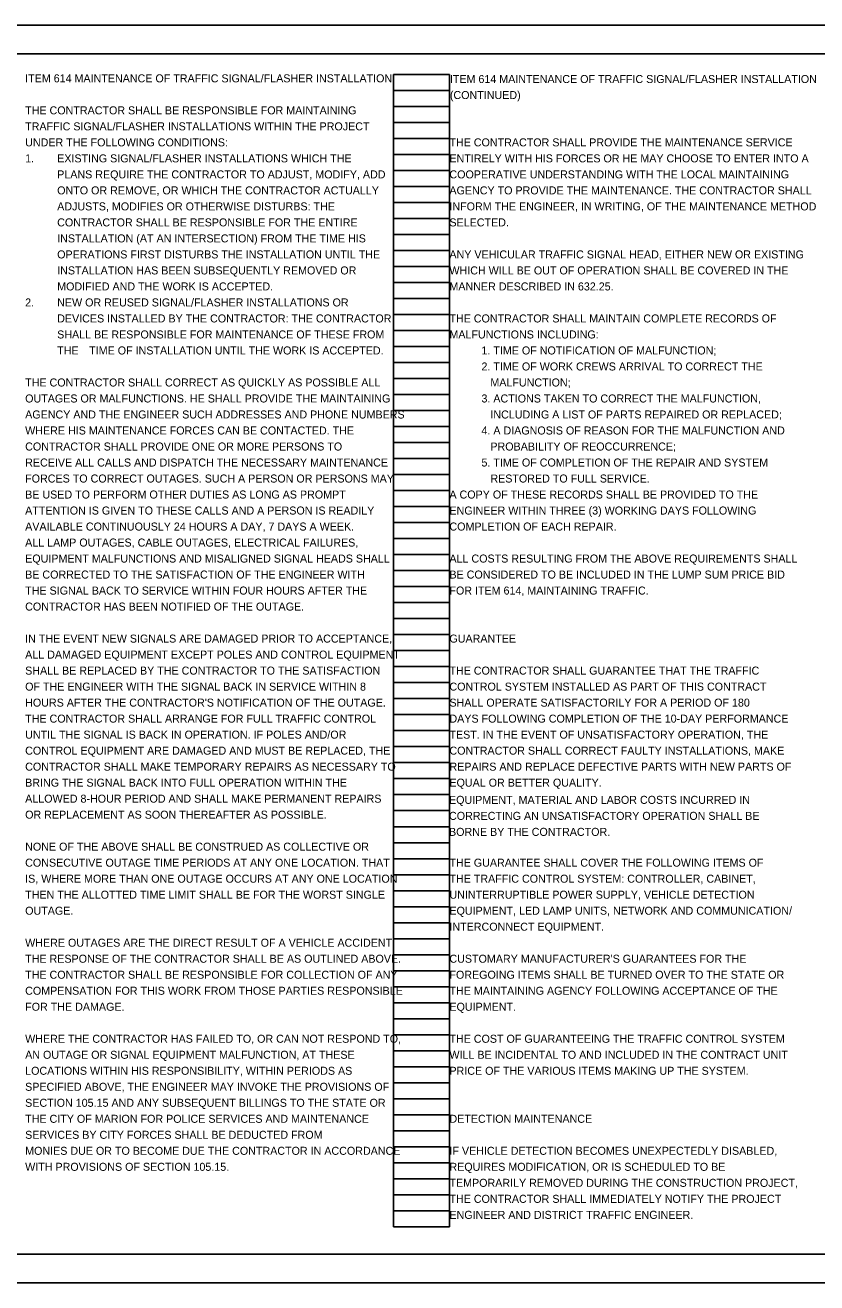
# Model space of a CAD drawing. Extents: x -11.8 to 65.2, y -26.4 to 34.6.
# Drawn here: x 10.32 to 24.17, y 0 to 22 of the extents above; entities that cross this region are included whole.
import ezdxf

# ---------------------------------------------------------------- set-up
doc = ezdxf.new("R2010")
doc.units = 0
for name, color, linetype in [('SH_Border', 7, 'Continuous'), ('SH_Cut_Line', 7, 'Continuous'), ('SH_Data', 7, 'Continuous'), ('SH_Text', 7, 'Continuous')]:
    doc.layers.add(name, color=color, linetype=linetype)

msp = doc.modelspace()

# ---------------------------------------------------------------- linework, layer by layer
at = {"layer": 'SH_Border'}
msp.add_lwpolyline([(2.001, 21.5), (33.501, 21.5), (33.501, 0.5), (2.001, 0.5)], close=True, dxfattribs=at)
at = {"layer": 'SH_Cut_Line'}
msp.add_lwpolyline([(0.001, 0), (34.001, 0), (34.001, 22), (0.001, 22)], close=True, dxfattribs=at)
at = {"layer": 'SH_Data'}
for p, q in [((16.761, 0.98), (16.761, 21.14)), ((16.761, 21.14), (17.741, 21.14)), ((17.741, 0.98), (17.741, 21.14)), ((16.761, 20.86), (17.741, 20.86)), ((16.761, 20.58), (17.741, 20.58)), ((16.761, 20.3), (17.741, 20.3)), ((16.761, 20.02), (17.741, 20.02)), ((16.761, 19.74), (17.741, 19.74)), ((16.761, 19.46), (17.741, 19.46)), ((16.761, 19.18), (17.741, 19.18)), ((16.761, 18.9), (17.741, 18.9)), ((16.761, 18.62), (17.741, 18.62)), ((16.761, 18.34), (17.741, 18.34)), ((16.761, 18.06), (17.741, 18.06)), ((16.761, 17.78), (17.741, 17.78)), ((16.761, 17.5), (17.741, 17.5)), ((16.761, 17.22), (17.741, 17.22)), ((16.761, 16.94), (17.741, 16.94)), ((16.761, 16.66), (17.741, 16.66)), ((16.761, 16.38), (17.741, 16.38)), ((16.761, 16.1), (17.741, 16.1)), ((16.761, 15.82), (17.741, 15.82)), ((16.761, 15.54), (17.741, 15.54)), ((16.761, 15.26), (17.741, 15.26)), ((16.761, 14.98), (17.741, 14.98)), ((16.761, 14.7), (17.741, 14.7)), ((16.761, 14.42), (17.741, 14.42)), ((16.761, 14.14), (17.741, 14.14)), ((16.761, 13.86), (17.741, 13.86)), ((16.761, 13.58), (17.741, 13.58)), ((16.761, 13.3), (17.741, 13.3)), ((16.761, 13.02), (17.741, 13.02)), ((16.761, 12.74), (17.741, 12.74)), ((16.761, 12.46), (17.741, 12.46)), ((16.761, 12.18), (17.741, 12.18)), ((16.761, 11.9), (17.741, 11.9)), ((16.761, 11.62), (17.741, 11.62)), ((16.761, 11.34), (17.741, 11.34)), ((16.761, 11.06), (17.741, 11.06)), ((16.761, 10.78), (17.741, 10.78)), ((16.761, 10.5), (17.741, 10.5)), ((16.761, 10.22), (17.741, 10.22)), ((16.761, 9.94), (17.741, 9.94)), ((16.761, 9.66), (17.741, 9.66)), ((16.761, 9.38), (17.741, 9.38)), ((16.761, 9.1), (17.741, 9.1)), ((16.761, 8.82), (17.741, 8.82)), ((16.761, 8.54), (17.741, 8.54)), ((16.761, 8.26), (17.741, 8.26)), ((16.761, 7.98), (17.741, 7.98)), ((16.761, 7.7), (17.741, 7.7)), ((16.761, 7.42), (17.741, 7.42)), ((16.761, 7.14), (17.741, 7.14)), ((16.761, 6.86), (17.741, 6.86)), ((16.761, 6.58), (17.741, 6.58)), ((16.761, 6.3), (17.741, 6.3)), ((16.761, 6.02), (17.741, 6.02)), ((16.761, 5.74), (17.741, 5.74)), ((16.761, 5.46), (17.741, 5.46)), ((16.761, 5.18), (17.741, 5.18)), ((16.761, 4.9), (17.741, 4.9)), ((16.761, 4.62), (17.741, 4.62)), ((16.761, 4.34), (17.741, 4.34)), ((16.761, 4.06), (17.741, 4.06)), ((16.761, 3.78), (17.741, 3.78)), ((16.761, 3.5), (17.741, 3.5)), ((16.761, 3.22), (17.741, 3.22)), ((16.761, 2.94), (17.741, 2.94)), ((16.761, 2.66), (17.741, 2.66)), ((16.761, 2.38), (17.741, 2.38)), ((16.761, 2.1), (17.741, 2.1)), ((16.761, 1.82), (17.741, 1.82)), ((16.761, 1.54), (17.741, 1.54)), ((16.761, 1.26), (17.741, 1.26)), ((16.761, 0.98), (17.741, 0.98))]:
    msp.add_line(p, q, dxfattribs=at)

# ---------------------------------------------------------------- texts
at = {"layer": 'SH_Text'}
for s, p in [('ITEM 614 MAINTENANCE OF TRAFFIC SIGNAL/FLASHER INSTALLATION', (10.321, 21)), ('ITEM 614 MAINTENANCE OF TRAFFIC SIGNAL/FLASHER INSTALLATION', (17.749, 20.988)), ('(CONTINUED)', (17.749, 20.708)), ('THE CONTRACTOR SHALL BE RESPONSIBLE FOR MAINTAINING ', (10.321, 20.44)), ('TRAFFIC SIGNAL/FLASHER INSTALLATIONS WITHIN THE PROJECT ', (10.321, 20.16)), ('UNDER THE FOLLOWING CONDITIONS:', (10.321, 19.88)), ('THE CONTRACTOR SHALL PROVIDE THE MAINTENANCE SERVICE ', (17.741, 19.88)), ('1.', (10.321, 19.6)), ('EXISTING SIGNAL/FLASHER INSTALLATIONS WHICH THE ', (10.881, 19.6)), ('ENTIRELY WITH HIS FORCES OR HE MAY CHOOSE TO ENTER INTO A ', (17.741, 19.6)), ('PLANS REQUIRE THE CONTRACTOR TO ADJUST, MODIFY, ADD ', (10.881, 19.32)), ('COOPERATIVE UNDERSTANDING WITH THE LOCAL MAINTAINING ', (17.741, 19.32)), ('ONTO OR REMOVE, OR WHICH THE CONTRACTOR ACTUALLY ', (10.881, 19.04)), ('AGENCY TO PROVIDE THE MAINTENANCE. THE CONTRACTOR SHALL ', (17.741, 19.04)), ('ADJUSTS, MODIFIES OR OTHERWISE DISTURBS: THE ', (10.881, 18.76)), ('INFORM THE ENGINEER, IN WRITING, OF THE MAINTENANCE METHOD ', (17.741, 18.76)), ('CONTRACTOR SHALL BE RESPONSIBLE FOR THE ENTIRE ', (10.881, 18.48)), ('SELECTED. ', (17.741, 18.48)), ('INSTALLATION (AT AN INTERSECTION) FROM THE TIME HIS ', (10.881, 18.2)), ('OPERATIONS FIRST DISTURBS THE INSTALLATION UNTIL THE ', (10.881, 17.92)), ('ANY VEHICULAR TRAFFIC SIGNAL HEAD, EITHER NEW OR EXISTING ', (17.741, 17.92)), ('INSTALLATION HAS BEEN SUBSEQUENTLY REMOVED OR ', (10.881, 17.64)), ('WHICH WILL BE OUT OF OPERATION SHALL BE COVERED IN THE ', (17.741, 17.64)), ('MODIFIED AND THE WORK IS ACCEPTED.', (10.881, 17.36)), ('MANNER DESCRIBED IN 632.25.', (17.741, 17.36)), ('2.', (10.321, 17.08)), ('NEW OR REUSED SIGNAL/FLASHER INSTALLATIONS OR ', (10.881, 17.08)), ('DEVICES INSTALLED BY THE CONTRACTOR: THE CONTRACTOR ', (10.881, 16.8)), ('THE CONTRACTOR SHALL MAINTAIN COMPLETE RECORDS OF ', (17.741, 16.8)), ('SHALL BE RESPONSIBLE FOR MAINTENANCE OF THESE FROM ', (10.881, 16.52)), ('MALFUNCTIONS INCLUDING:', (17.741, 16.52)), ('THE ', (10.881, 16.24)), ('TIME OF INSTALLATION UNTIL THE WORK IS ACCEPTED. ', (11.441, 16.24)), ('1. TIME OF NOTIFICATION OF MALFUNCTION;', (18.301, 16.24)), ('2. TIME OF WORK CREWS ARRIVAL TO CORRECT THE ', (18.301, 15.96)), ('THE CONTRACTOR SHALL CORRECT AS QUICKLY AS POSSIBLE ALL ', (10.321, 15.68)), ('   MALFUNCTION;', (18.301, 15.68)), ('OUTAGES OR MALFUNCTIONS. HE SHALL PROVIDE THE MAINTAINING ', (10.321, 15.4)), ('3. ACTIONS TAKEN TO CORRECT THE MALFUNCTION, ', (18.301, 15.4)), ('AGENCY AND THE ENGINEER SUCH ADDRESSES AND PHONE NUMBERS ', (10.321, 15.12)), ('   INCLUDING A LIST OF PARTS REPAIRED OR REPLACED;', (18.301, 15.12)), ('WHERE HIS MAINTENANCE FORCES CAN BE CONTACTED. THE ', (10.321, 14.84)), ('4. A DIAGNOSIS OF REASON FOR THE MALFUNCTION AND ', (18.301, 14.84)), ('CONTRACTOR SHALL PROVIDE ONE OR MORE PERSONS TO', (10.321, 14.56)), ('   PROBABILITY OF REOCCURRENCE;', (18.301, 14.56)), ('RECEIVE ALL CALLS AND DISPATCH THE NECESSARY MAINTENANCE ', (10.321, 14.28)), ('5. TIME OF COMPLETION OF THE REPAIR AND SYSTEM ', (18.301, 14.28)), ('FORCES TO CORRECT OUTAGES. SUCH A PERSON OR PERSONS MAY ', (10.321, 14)), ('   RESTORED TO FULL SERVICE.', (18.301, 14)), ('BE USED TO PERFORM OTHER DUTIES AS LONG AS PROMPT ', (10.321, 13.72)), ('A COPY OF THESE RECORDS SHALL BE PROVIDED TO THE ', (17.741, 13.72)), ('ATTENTION IS GIVEN TO THESE CALLS AND A PERSON IS READILY ', (10.321, 13.44)), ('ENGINEER WITHIN THREE (3) WORKING DAYS FOLLOWING ', (17.741, 13.44)), ('AVAILABLE CONTINUOUSLY 24 HOURS A DAY, 7 DAYS A WEEK. ', (10.321, 13.16)), ('COMPLETION OF EACH REPAIR.', (17.741, 13.16)), ('ALL LAMP OUTAGES, CABLE OUTAGES, ELECTRICAL FAILURES, ', (10.321, 12.88)), ('EQUIPMENT MALFUNCTIONS AND MISALIGNED SIGNAL HEADS SHALL ', (10.321, 12.6)), ('ALL COSTS RESULTING FROM THE ABOVE REQUIREMENTS SHALL ', (17.741, 12.6)), ('BE CORRECTED TO THE SATISFACTION OF THE ENGINEER WITH ', (10.321, 12.32)), ('BE CONSIDERED TO BE INCLUDED IN THE LUMP SUM PRICE BID ', (17.741, 12.32)), ('THE SIGNAL BACK TO SERVICE WITHIN FOUR HOURS AFTER THE ', (10.321, 12.04)), ('FOR ITEM 614, MAINTAINING TRAFFIC. ', (17.741, 12.04)), ('CONTRACTOR HAS BEEN NOTIFIED OF THE OUTAGE.', (10.321, 11.76)), ('IN THE EVENT NEW SIGNALS ARE DAMAGED PRIOR TO ACCEPTANCE, ', (10.321, 11.2)), ('GUARANTEE', (17.741, 11.2)), ('ALL DAMAGED EQUIPMENT EXCEPT POLES AND CONTROL EQUIPMENT ', (10.321, 10.92)), ('SHALL BE REPLACED BY THE CONTRACTOR TO THE SATISFACTION ', (10.321, 10.64)), ('THE CONTRACTOR SHALL GUARANTEE THAT THE TRAFFIC', (17.741, 10.64)), ('OF THE ENGINEER WITH THE SIGNAL BACK IN SERVICE WITHIN 8 ', (10.321, 10.36)), ('CONTROL SYSTEM INSTALLED AS PART OF THIS CONTRACT', (17.741, 10.36)), ("HOURS AFTER THE CONTRACTOR'S NOTIFICATION OF THE OUTAGE. ", (10.321, 10.08)), ('SHALL OPERATE SATISFACTORILY FOR A PERIOD OF 180', (17.741, 10.08)), ('THE CONTRACTOR SHALL ARRANGE FOR FULL TRAFFIC CONTROL ', (10.321, 9.8)), ('DAYS FOLLOWING COMPLETION OF THE 10-DAY PERFORMANCE', (17.741, 9.8)), ('UNTIL THE SIGNAL IS BACK IN OPERATION. IF POLES AND/OR ', (10.321, 9.52)), ('TEST. IN THE EVENT OF UNSATISFACTORY OPERATION, THE', (17.741, 9.52)), ('CONTROL EQUIPMENT ARE DAMAGED AND MUST BE REPLACED, THE ', (10.321, 9.24)), ('CONTRACTOR SHALL CORRECT FAULTY INSTALLATIONS, MAKE', (17.741, 9.24)), ('CONTRACTOR SHALL MAKE TEMPORARY REPAIRS AS NECESSARY TO ', (10.321, 8.96)), ('REPAIRS AND REPLACE DEFECTIVE PARTS WITH NEW PARTS OF', (17.741, 8.96)), ('BRING THE SIGNAL BACK INTO FULL OPERATION WITHIN THE ', (10.321, 8.68)), ('EQUAL OR BETTER QUALITY.', (17.741, 8.68)), ('ALLOWED 8-HOUR PERIOD AND SHALL MAKE PERMANENT REPAIRS ', (10.321, 8.4)), ('EQUIPMENT, MATERIAL AND LABOR COSTS INCURRED IN', (17.734, 8.379)), ('OR REPLACEMENT AS SOON THEREAFTER AS POSSIBLE.', (10.321, 8.12)), ('CORRECTING AN UNSATISFACTORY OPERATION SHALL BE', (17.734, 8.099)), ('BORNE BY THE CONTRACTOR.', (17.734, 7.819)), ('NONE OF THE ABOVE SHALL BE CONSTRUED AS COLLECTIVE OR ', (10.321, 7.56)), ('CONSECUTIVE OUTAGE TIME PERIODS AT ANY ONE LOCATION. THAT ', (10.321, 7.28)), ('THE GUARANTEE SHALL COVER THE FOLLOWING ITEMS OF', (17.741, 7.28)), ('IS, WHERE MORE THAN ONE OUTAGE OCCURS AT ANY ONE LOCATION ', (10.321, 7)), ('THE TRAFFIC CONTROL SYSTEM: CONTROLLER, CABINET,', (17.741, 7)), ('THEN THE ALLOTTED TIME LIMIT SHALL BE FOR THE WORST SINGLE ', (10.321, 6.72)), ('UNINTERRUPTIBLE POWER SUPPLY, VEHICLE DETECTION', (17.741, 6.72)), ('OUTAGE.', (10.321, 6.44)), ('EQUIPMENT, LED LAMP UNITS, NETWORK AND COMMUNICATION/', (17.741, 6.44)), ('INTERCONNECT EQUIPMENT.', (17.741, 6.16)), ('WHERE OUTAGES ARE THE DIRECT RESULT OF A VEHICLE ACCIDENT ', (10.321, 5.88)), ('THE RESPONSE OF THE CONTRACTOR SHALL BE AS OUTLINED ABOVE. ', (10.321, 5.6)), ("CUSTOMARY MANUFACTURER'S GUARANTEES FOR THE", (17.741, 5.6)), ('THE CONTRACTOR SHALL BE RESPONSIBLE FOR COLLECTION OF ANY ', (10.321, 5.32)), ('FOREGOING ITEMS SHALL BE TURNED OVER TO THE STATE OR', (17.741, 5.32)), ('COMPENSATION FOR THIS WORK FROM THOSE PARTIES RESPONSIBLE ', (10.321, 5.04)), ('THE MAINTAINING AGENCY FOLLOWING ACCEPTANCE OF THE', (17.741, 5.04)), ('FOR THE DAMAGE.', (10.321, 4.76)), ('EQUIPMENT.', (17.741, 4.76)), ('WHERE THE CONTRACTOR HAS FAILED TO, OR CAN NOT RESPOND TO, ', (10.321, 4.2)), ('THE COST OF GUARANTEEING THE TRAFFIC CONTROL SYSTEM', (17.741, 4.2)), ('AN OUTAGE OR SIGNAL EQUIPMENT MALFUNCTION, AT THESE ', (10.321, 3.92)), ('WILL BE INCIDENTAL TO AND INCLUDED IN THE CONTRACT UNIT', (17.741, 3.92)), ('LOCATIONS WITHIN HIS RESPONSIBILITY, WITHIN PERIODS AS ', (10.321, 3.64)), ('PRICE OF THE VARIOUS ITEMS MAKING UP THE SYSTEM.', (17.741, 3.64)), ('SPECIFIED ABOVE, THE ENGINEER MAY INVOKE THE PROVISIONS OF ', (10.321, 3.36)), ('SECTION 105.15 AND ANY SUBSEQUENT BILLINGS TO THE STATE OR ', (10.321, 3.08)), ('THE CITY OF MARION FOR POLICE SERVICES AND MAINTENANCE ', (10.321, 2.8)), ('DETECTION MAINTENANCE', (17.741, 2.8)), ('SERVICES BY CITY FORCES SHALL BE DEDUCTED FROM ', (10.321, 2.52)), ('MONIES DUE OR TO BECOME DUE THE CONTRACTOR IN ACCORDANCE ', (10.321, 2.24)), ('IF VEHICLE DETECTION BECOMES UNEXPECTEDLY DISABLED,', (17.741, 2.24)), ('WITH PROVISIONS OF SECTION 105.15.', (10.321, 1.96)), ('REQUIRES MODIFICATION, OR IS SCHEDULED TO BE', (17.741, 1.96)), ('TEMPORARILY REMOVED DURING THE CONSTRUCTION PROJECT,', (17.741, 1.68)), ('THE CONTRACTOR SHALL IMMEDIATELY NOTIFY THE PROJECT', (17.741, 1.4)), ('ENGINEER AND DISTRICT TRAFFIC ENGINEER.', (17.741, 1.12))]:
    msp.add_text(s, height=0.14, dxfattribs=at).set_placement(p)

doc.saveas('drawing.dxf')
